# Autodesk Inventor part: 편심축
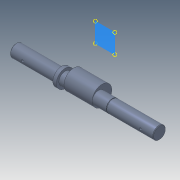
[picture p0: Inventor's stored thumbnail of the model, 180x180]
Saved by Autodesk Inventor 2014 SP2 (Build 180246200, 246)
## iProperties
Manager: 한국ATC센터
Company: 한국ATC센터
Created: 2014-10
Part Number: 편심축
Document SubType Name: Modeling
Designer: 한국ATC센터
Density: 7.86 g/cm^3
Material: 강철, 연강
Mass: 1140.06 g
Surface Area: 226.679 cm^2
Volume: 145.046 cm^3
Appearance: 강철
Author: KYOUNG IL JANG
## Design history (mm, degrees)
sketch "스케치1"
  geometry: L1 (-142, 0)-(142, 0); L2 (-142, 0)-(-142, 12.5); L3 (-142, 12.5)-(-52, 12.5); L4 (-52, 12.5)-(-52, 17.5); L5 (-52, 17.5)-(-45, 17.5); L6 (-45, 17.5)-(-45, 12.5); L7 (-45, 12.5)-(48.65, 12.5); L8 (48.65, 12.5)-(48.65, 11.95); L9 (48.65, 11.95)-(50, 11.95); L10 (50, 11.95)-(50, 12.5); L11 (50, 12.5)-(142, 12.5); L12 (142, 12.5)-(142, 0); L13 (109, 12.5)-(109, 9.1); L14 (109, 9.1)-(134, 9.1); L15 (134, 9.1)-(134, 12.5); L16 (117, -12.5)-(119.5, -12.5); L17 (119.5, -12.5)-(117, -10); L18 (117, -10)-(117, -12.5); L19 (-109, 12.5)-(-109, 9.1); L20 (-109, 9.1)-(-134, 9.1); L21 (-134, 9.1)-(-134, 12.5); L22 (-117, -12.5)-(-117, -10); L23 (-117, -10)-(-114.5, -12.5); L24 (-114.5, -12.5)-(-117, -12.5); 2 further points
  constraints: 48 end point, 11 parallel, 8 perpendicular, 5 collinear, 4 point on line, 1 coincident, 1 horizontal, 1 midpoint, 1 vertical
  dimensions: "d0" = 284 distance of L1.start L1.end (derived); "d1" = 25 diameter of L3 L1; "d2" = 35 diameter of L5 L1; "d3" = 90 distance of L2.end L3.end; "d4" = 187 distance between parallel lines of L12 L6; "d6" = 1.35 distance of L8.end L9.end; "d7" = 23.9 diameter of L9 L1; "d8" = 3.4 distance between parallel lines of L14 L11; "d9" = 8 distance between parallel lines of L15 L12; "d10" = 25 distance of L13.end L14.end; "d11" = 25 diameter of L16 L1 (= d1); "d12" = 25 distance from line of L12 L16.start; "d13" = 45 deg angle of L17 L18; "d14" = 5 diameter of L16.end L18; "d27" = 92 distance between parallel lines of L10 L12; "d32" = 7 distance of L4.end L5.end; "d33" = 8 distance between parallel lines of L2 L21; "d34" = 25 distance between parallel lines of L21 L19; "d35" = 3.4 distance between parallel lines of L3 L20; "d36" = 25 distance from line of L22.start L2; "d37" = 5 diameter of L23.end L22
revolve "회전1" stored, may be unused: angle "d15" = 90 deg
revolve "회전2" stored, may be unused: angle "d16" = 90 deg
revolve "회전3" stored, may be unused: angle "d38" = 90 deg
extrude "돌출1" cut sketch "스케치1" stored distance "d17" = 8; taper "d18" = 0 deg
fillet "모깎기1" dims "d19" = 4
node "작업 평면1"
sketch "스케치2"
  geometry: C1 r 12.5 at (0, 0) reference; C2 r 19.5 at (0, 7); 1 further point
  constraints: 1 centre point, 1 tangent, 1 vertical alignment
  dimensions: "d21" = 7 distance of point (0, 0) C2.centre; "d30" = 39 diameter of C2 (derived)
extrude "돌출2" join sketch "스케치2" distance "d22" = 56; taper "d23" = 0 deg
chamfer "모따기1" distance "d24" = 1; stored, may be unused: second distance "d25" = 2, angle "d26" = 45 deg
node "솔리드1"
other parameters: "d20" = 16
